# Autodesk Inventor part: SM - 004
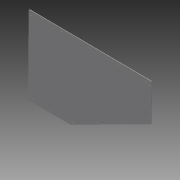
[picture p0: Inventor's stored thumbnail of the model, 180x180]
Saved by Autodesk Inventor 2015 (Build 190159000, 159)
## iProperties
Created: 2007-02
Part Number: SM - 004
Material: Steel
Document SubType Name: Sheet Metal
Designer: Autodesk, Inc.
Mass: 9160.63 g
Surface Area: 7744.64 cm^2
Volume: 1166.96 cm^3
Density: 7.85 g/cm^3
Description: =Drive Casing Cover - <Material>
Sheet Metal Rule: Default
Appearance: Steel
Author: Autodesk, Inc.
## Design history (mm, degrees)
node "Face1"
  sketch "Sketch1"
    geometry: L1 (-820.33, -281.463)-(-815.069, 252.994) reference; L2 (-523.21, -289.591)-(-815.178, -286.718) reference; L3 (27.649, -10.922)-(-520.298, -285.682); L4 (-815.018, 258.197)-(34.941, 249.831) reference; L5 (34.89, 244.628)-(32.398, -8.541) reference; L6 (34.941, 249.831)-(-815.018, 258.197); L7 (-815.018, 258.197)-(-820.381, -286.666); L8 (-820.381, -286.666)-(-528.001, -289.544); L9 (-528.001, -289.544)-(32.398, -8.541); L10 (32.398, -8.541)-(34.941, 249.831)
    constraints: 13 end point, 5 collinear, 2 parallel
fillet "Fillet1" dims "d1" = 6.35
sketch "Sketch2"
  geometry: 4 further points
hole "Hole1" sketch "Sketch2" at (-799.445, 227.439), (-801.031, 66.301), (-802.617, -94.837), (-804.203, -255.975) diameter "d2" = 5.1054; stored, may be unused: countersink angle "d6" = 82 deg, drill point angle "d8" = 0 deg; dims "d3" = 12.7, "d4" = 9.525, "d5" = 6.35, "d7" = 19.05
sketch "Sketch3"
  geometry: 5 further points
hole "Hole2" sketch "Sketch3" at (-783.426, 242.011), (-587.887, 240.086), (-392.348, 238.161), (-196.81, 236.237), (-1.271, 234.312) diameter "d9" = 5.1054; stored, may be unused: countersink angle "d13" = 82 deg, drill point angle "d15" = 0 deg; dims "d10" = 12.7, "d11" = 9.525, "d12" = 6.35, "d14" = 19.05
sketch "Sketch4"
  geometry: 3 further points
hole "Hole3" sketch "Sketch4" at (-788.476, -271.105), (-662.714, -272.343), (-536.952, -273.58) diameter "d16" = 5.1054; stored, may be unused: countersink angle "d20" = 82 deg, drill point angle "d22" = 0 deg; dims "d17" = 12.7, "d18" = 9.525, "d19" = 6.35, "d21" = 19.05
sketch "Sketch5"
  geometry: 4 further points
hole "Hole4" sketch "Sketch5" at (-511.769, -267.274), (-340.472, -181.38), (-169.175, -95.485), (2.122, -9.591) diameter "d23" = 5.1054; stored, may be unused: countersink angle "d27" = 82 deg, drill point angle "d29" = 0 deg; dims "d24" = 12.7, "d25" = 9.525, "d26" = 6.35, "d28" = 19.05
sketch "Sketch6"
  geometry: 3 further points
hole "Hole5" sketch "Sketch6" at (18.754, 218.239), (17.748, 115.996), (16.741, 13.753) diameter "d30" = 5.1054; stored, may be unused: countersink angle "d34" = 82 deg, drill point angle "d36" = 0 deg; dims "d31" = 12.7, "d32" = 9.525, "d33" = 6.35, "d35" = 19.05
body "Solid1"
node "Reference1"
node "Reference2"
node "Reference4"
node "Reference5"
face "Plate1" dims "Thickness" = 3.048
other parameters: "BendRadius" = 3.048 (= Thickness), "BendReliefWidth" = 3.048 (= Thickness), "BendReliefDepth" = 1.524 (= 0.5 x Thickness), "CornerReliefSize" = 12.192 (= 4 x Thickness), "SeamGap" = 0.00508, "MinimumRemnant" = 6.096 (= 2 x Thickness), "TransitionRadius" = 3.048 (= BendRadius), "JacobiRadiusSize" = 3.048 (= Thickness), "d0" = 3.048 (= BendRadius), "GapSize" = 3.048 (= Thickness)
